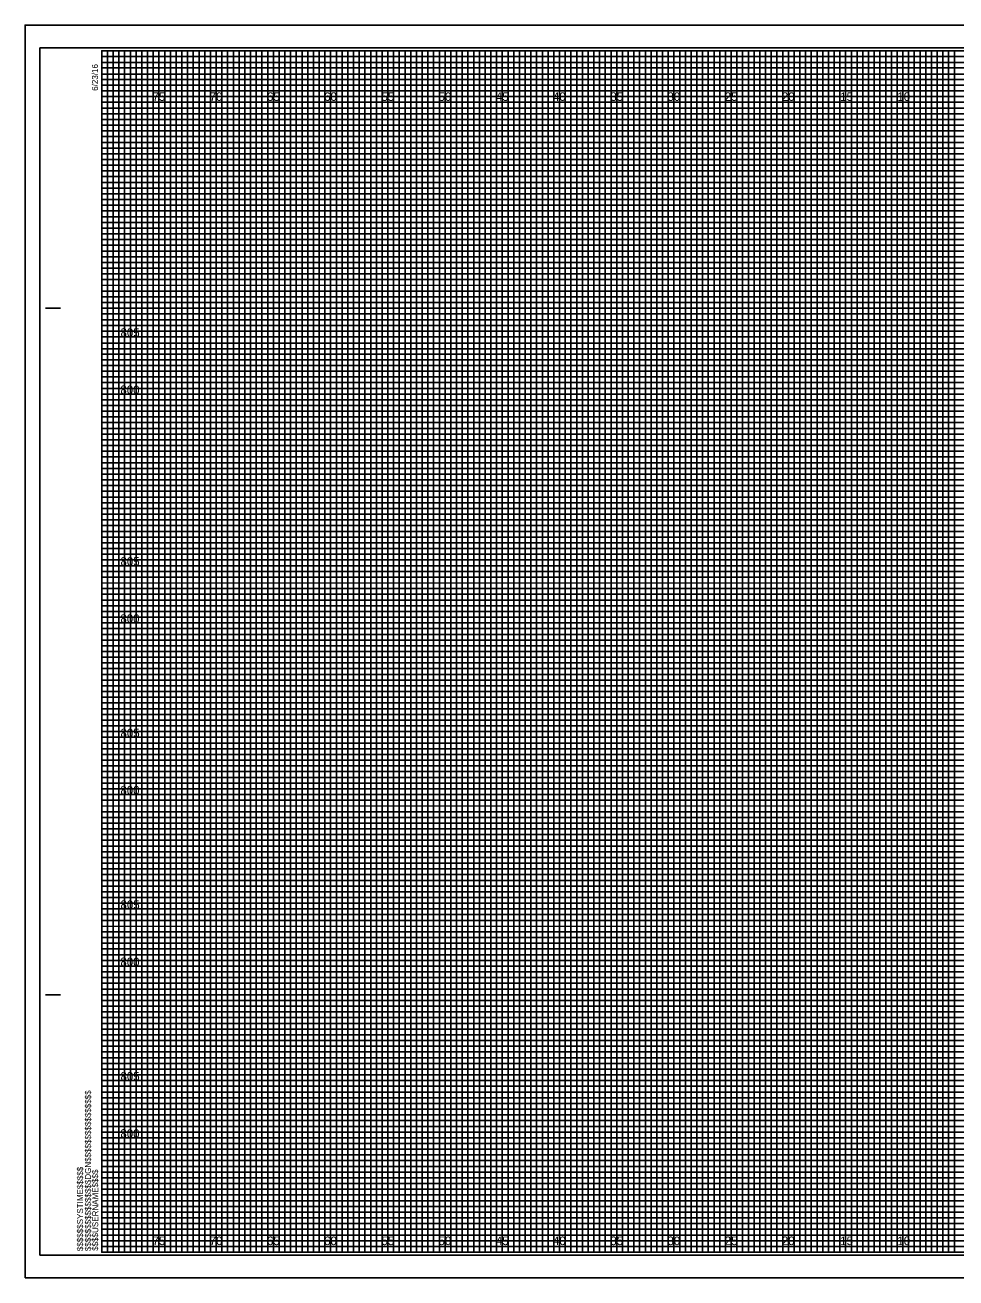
# Model space of a CAD drawing. Extents: x -7 to 162, y -2 to 107.
# Drawn here: x -6.7 to 74.6, y -2.3 to 107.3 of the extents above; entities that cross this region are included whole.
import ezdxf

# ---------------------------------------------------------------- set-up
doc = ezdxf.new("R2010")
doc.units = 0
for name, color, linetype in [('Exist Cross Section Cell', 7, 'Continuous'), ('Exist XS Center Line Elevation Label', 7, 'Continuous'), ('Prop CMT Pvmt Course 1 Wedge', 7, 'Continuous'), ('Prop CMT Pvmt Wedge Surface 1', 7, 'Continuous'), ('Prop XS Hydro Elevations', 7, 'Continuous'), ('Prop XS SE Text', 7, 'Continuous'), ('Prop XS Side Slope Text', 7, 'Continuous'), ('Sheet Cross Section Grid Minor 2 CELL', 7, 'Continuous'), ('Sheet DOT Grid CELL', 7, 'Continuous'), ('Sheet Plot Border Inside CELL', 7, 'Continuous'), ('Sheet Plot Border Outside CELL', 7, 'Continuous')]:
    doc.layers.add(name, color=color, linetype=linetype)

msp = doc.modelspace()

# ---------------------------------------------------------------- linework, layer by layer
at = {"layer": 'Exist Cross Section Cell'}
for p, q in [((5, 105), (0, 105)), ((5, 0), (5, 105)), ((15, 105), (10, 105)), ((10, 105), (10, 0)), ((15, 0), (15, 105)), ((25, 105), (20, 105)), ((20, 105), (20, 0)), ((25, 0), (25, 105)), ((35, 105), (30, 105)), ((30, 105), (30, 0)), ((35, 0), (35, 105)), ((45, 105), (40, 105)), ((40, 105), (40, 0)), ((45, 0), (45, 105)), ((55, 105), (50, 105)), ((50, 105), (50, 0)), ((55, 0), (55, 105)), ((65, 105), (60, 105)), ((60, 105), (60, 0)), ((65, 0), (65, 105)), ((75, 105), (70, 105)), ((70, 105), (70, 0)), ((10, 0), (5, 0)), ((20, 0), (15, 0)), ((30, 0), (25, 0)), ((40, 0), (35, 0)), ((50, 0), (45, 0)), ((60, 0), (55, 0)), ((70, 0), (65, 0))]:
    msp.add_line(p, q, dxfattribs=at)
for points in [[(0, 100), (160, 100), (160, 95), (0, 95)], [(0, 90), (160, 90), (160, 85), (0, 85)], [(0, 80), (160, 80), (160, 75), (0, 75)], [(0, 70), (160, 70), (160, 65), (0, 65)], [(0, 60), (160, 60), (160, 55), (0, 55)], [(0, 50), (160, 50), (160, 45), (0, 45)], [(0, 40), (160, 40), (160, 35), (0, 35)], [(0, 30), (160, 30), (160, 25), (0, 25)], [(0, 20), (160, 20), (160, 15), (0, 15)], [(0, 10), (160, 10), (160, 5), (0, 5)]]:
    msp.add_lwpolyline(points, dxfattribs=at)
at = {"layer": 'Exist XS Center Line Elevation Label'}
for points in [[(0, 105), (2.5, 105), (2.5, 0), (7.5, 0), (7.5, 105), (12.5, 105), (12.5, 0), (17.5, 0), (17.5, 105), (22.5, 105), (22.5, 0), (27.5, 0), (27.5, 105), (32.5, 105), (32.5, 0), (37.5, 0), (37.5, 105), (42.5, 105), (42.5, 0), (47.5, 0), (47.5, 105), (52.5, 105), (52.5, 0), (57.5, 0), (57.5, 105), (62.5, 105), (62.5, 0), (67.5, 0), (67.5, 105), (72.5, 105), (72.5, 0), (77.5, 0)], [(0, 102.5), (137.5, 102.5)], [(0, 92.5), (160, 92.5), (160, 97.5), (0, 97.5)], [(0, 82.5), (160, 82.5), (160, 87.5), (0, 87.5)], [(0, 72.5), (160, 72.5), (160, 77.5), (0, 77.5)], [(0, 62.5), (160, 62.5), (160, 67.5), (0, 67.5)], [(0, 52.5), (160, 52.5), (160, 57.5), (0, 57.5)], [(0, 42.5), (160, 42.5), (160, 47.5), (0, 47.5)], [(0, 32.5), (160, 32.5), (160, 37.5), (0, 37.5)], [(0, 22.5), (160, 22.5), (160, 27.5), (0, 27.5)], [(0, 12.5), (160, 12.5), (160, 17.5), (0, 17.5)], [(0, 2.5), (160, 2.5), (160, 7.5), (0, 7.5)]]:
    msp.add_lwpolyline(points, dxfattribs=at)
at = {"layer": 'Prop CMT Pvmt Wedge Surface 1'}
for p, q in [((161.65, 107.25), (-6.7, 107.25)), ((-6.7, 107.25), (-6.7, -2.25)), ((-6.7, -2.25), (161.65, -2.25))]:
    msp.add_line(p, q, dxfattribs=at)
at = {"layer": 'Prop XS Hydro Elevations'}
for p, q in [((-4.9, 82.5), (-3.65, 82.5)), ((-4.85, 82.5), (-3.6, 82.5)), ((-4.9, 22.5), (-3.65, 22.5)), ((-4.85, 22.5), (-3.6, 22.5)), ((0, 0), (0, 0)), ((0, 0), (0, 0)), ((0, 0), (0, 0)), ((0, 0), (0, 0)), ((0, 0), (0, 0)), ((0, 0), (0, 0)), ((0, 0), (0, 0))]:
    msp.add_line(p, q, dxfattribs=at)
msp.add_lwpolyline([(160, 105), (0, 105), (0, 0), (160, 0)], close=True, dxfattribs=at)
at = {"layer": 'Prop XS Side Slope Text'}
for p, q in [((0, 104.5), (130, 104.5)), ((130, 103.99), (0, 103.99)), ((0, 103.99), (0, 103.5)), ((0, 103.5), (130, 103.5)), ((130, 102.95), (0, 102.95)), ((0, 102.95), (0, 102)), ((0, 102), (160, 102))]:
    msp.add_line(p, q, dxfattribs=at)
for points in [[(0, 101.5), (135, 101.5), (160, 101.5), (160, 101), (0, 101)], [(0, 100.5), (160, 100.5), (160, 99.5), (0, 99.5)], [(0, 99), (160, 99), (160, 98.5), (0, 98.49)], [(0, 98), (160, 98), (160, 97), (0, 97)], [(0, 96.5), (160, 96.5), (160, 96), (0, 96)], [(0, 95.5), (160, 95.5), (160, 94.5), (0, 94.5)], [(0, 94), (160, 94), (160, 93.5), (0, 93.5)], [(0, 93), (160, 93), (160, 92), (0, 92)], [(0, 91.5), (160, 91.5), (160, 91), (0, 91)], [(0, 90.5), (160, 90.5), (160, 89.5), (0, 89.5)], [(0, 89), (160, 89), (160, 88.5), (0, 88.5)], [(0, 88), (160, 88), (160, 86.98), (160, 86.5), (160, 86), (0, 86)], [(0, 87), (160, 87), (160, 86.5), (0, 86.5)], [(0, 85.5), (160, 85.5), (160, 84.5), (0, 84.52)], [(0, 84.52), (160, 84.5), (160, 84), (0, 84)], [(0, 83.5), (160, 83.5), (160, 83), (0, 83)], [(0, 82), (160, 82), (160, 81.5), (0, 81.5)], [(0, 81), (160, 81), (160, 80.5), (0, 80.5)], [(-0.04, 79.45), (160, 79.45), (160, 78.94), (-0.04, 78.94)], [(0, 78.5), (160, 78.5), (160, 78), (0, 78)], [(0, 77), (160, 77), (160, 76.5), (0, 76.5)], [(0, 76), (160, 76), (160, 75.5), (0, 75.5)], [(0, 74.5), (160, 74.5), (160, 74), (0, 74)], [(0, 73.5), (160, 73.5), (160, 73), (0, 73)], [(0, 72), (160, 72), (160, 71.5), (0, 71.5)], [(0, 71), (160, 71), (160, 70.5), (0, 70.5)], [(0, 69.5), (160, 69.5), (160, 68.99), (0, 69)], [(0, 68.5), (160, 68.5), (160, 68), (0, 68)], [(0, 67), (160, 67), (160, 66.5), (0, 66.5)], [(0, 66), (160, 66), (160, 65.5), (0, 65.5)], [(0, 64.5), (160, 64.5), (160, 64), (0, 64)], [(0, 63.5), (160, 63.5), (160, 63), (0, 63)], [(0, 62), (160, 62), (160, 61.5), (0, 61.5)], [(0, 61), (160, 61), (160, 60.5), (0, 60.5)], [(0, 59.5), (160, 59.5), (160, 59), (0, 59)], [(0, 58.5), (160.03, 58.45), (160, 58), (0, 58)], [(0, 57), (160, 57), (160, 56.5), (0, 56.5)], [(0, 56), (160, 56), (160, 55.5), (0, 55.5)], [(0, 54.5), (160, 54.5), (160, 54), (0, 54)], [(0, 53.5), (160, 53.5), (160, 53), (0, 53)], [(0, 52), (160, 52), (160, 51.5), (0, 51.5)], [(0, 51), (160, 51), (160, 50.5), (0, 50.5)], [(0, 49.5), (160, 49.5), (160, 49), (0, 49)], [(0, 48.5), (160, 48.5), (160, 48), (0, 48)], [(0, 47), (160, 47), (160, 46.5), (0, 46.5)], [(0, 46), (160, 46), (160, 45.5), (0, 45.5)], [(0, 44.5), (160, 44.5), (160, 44), (0, 44)], [(0, 43.5), (160, 43.5), (160, 43), (0, 43)], [(0, 42), (160, 42), (160, 41.5), (0, 41.5)], [(0, 41), (160, 41), (160, 40.5), (0, 40.5)], [(0, 39.5), (160, 39.5), (160, 38.99), (0, 39)], [(0, 38.5), (160, 38.5), (160, 38), (0, 38)], [(0, 37), (160, 37), (160, 36.5), (0, 36.5)], [(0, 36), (160, 36), (160, 35.5), (0, 35.5)], [(0, 34.5), (160, 34.5), (160, 34), (0, 34)], [(0, 33.5), (160, 33.5), (160, 33), (0, 33)], [(0, 32), (160, 32), (160, 31.5), (0, 31.5)], [(0, 31), (160, 31), (160, 30.5), (0, 30.5)], [(0, 29.5), (160, 29.5), (160, 29), (0, 29)], [(0, 28.5), (160.03, 28.46), (160, 28), (0, 28)], [(0, 27), (160, 27), (160, 26.5), (0, 26.5)], [(0, 26), (160, 26), (160, 25.5), (0, 25.5)], [(0, 24.5), (160, 24.5), (160, 24), (0, 24)], [(0, 23.5), (160, 23.5), (160, 23), (0, 23)], [(0, 22), (160, 22), (160, 21.5), (0, 21.5)], [(0, 21), (160, 21), (160, 20.5), (0, 20.5)], [(0, 19.5), (160, 19.5), (160, 19), (0, 19)], [(0, 18.5), (160, 18.5), (160, 18), (0, 18)], [(0, 17), (160, 17), (160, 16.5), (0, 16.5)], [(0, 16), (160, 16), (160, 15.5), (0, 15.5)], [(0, 14.5), (160, 14.5), (160, 14), (0, 14)], [(0, 13.5), (160, 13.5), (160, 13), (0, 13)], [(0, 12), (160, 12), (160, 11.5), (0, 11.5)], [(0, 11), (160, 11), (160, 10.5), (0, 10.5)], [(0, 9.5), (160, 9.5), (160, 9), (0, 9)], [(0, 8.5), (160, 8.5), (160, 8), (0, 8)], [(0, 7), (160, 7), (160, 6.5), (0, 6.5)], [(0, 6), (160, 6), (160, 5.5), (0, 5.5)], [(0, 4.5), (160, 4.5), (160, 4), (0, 4)], [(0, 3.5), (160, 3.5), (160, 3), (0, 3)], [(0, 2), (160, 2), (160, 1.5), (0, 1.5)], [(0, 1), (160, 1), (160, 0.5), (0, 0.5)]]:
    msp.add_lwpolyline(points, dxfattribs=at)
at = {"layer": 'Sheet Cross Section Grid Minor 2 CELL'}
for points in [[(0, 0), (0.5, 0), (0.5, 105), (1, 105), (1, 0)], [(1, 0), (1.5, 0), (1.5, 105), (2, 105), (2, 0)], [(2.5, 0), (3, 0), (3, 105), (3.5, 105), (3.5, 0)], [(3.5, 0), (4, 0), (4, 105), (4.5, 105), (4.5, 0)], [(5, 0), (5.5, 0), (5.5, 105), (6, 105), (6, 0)], [(6, 0), (6.5, 0), (6.5, 105), (7, 105), (7, 0)], [(7.5, 0), (8, 0), (8, 105), (8.5, 105), (8.5, 0)], [(8.5, 0), (9, 0), (9, 105), (9.5, 105), (9.5, 0)], [(10, 0), (10.5, 0), (10.5, 105), (11, 105), (11, 0)], [(11, 0), (11.5, 0), (11.5, 105), (12, 105), (12, 0)], [(12.5, 0), (13, 0), (13, 105), (13.5, 105), (13.5, 0)], [(13.5, 0), (14, 0), (14, 105), (14.5, 105), (14.5, 0)], [(15, 0), (15.5, 0), (15.5, 105), (16, 105), (16, 0)], [(16, 0), (16.5, 0), (16.5, 105), (17, 105), (17, 0)], [(17.5, 0), (18, 0), (18, 105), (18.5, 105), (18.5, 0)], [(18.5, 0), (19, 0), (19, 105), (19.5, 105), (19.5, 0)], [(20, 0), (20.5, 0), (20.5, 105), (21, 105), (21, 0)], [(21, 0), (21.5, 0), (21.5, 105), (22, 105), (22, 0)], [(22.5, 0), (23, 0), (23, 105), (23.5, 105), (23.5, 0)], [(23.5, 0), (24, 0), (24, 105), (24.5, 105), (24.5, 0)], [(25, 0), (25.5, 0), (25.5, 105), (26, 105), (26, 0)], [(26, 0), (26.5, 0), (26.5, 105), (27, 105), (27, 0)], [(27.5, 0), (28, 0), (28, 105), (28.5, 105), (28.5, 0)], [(28.5, 0), (29, 0), (29, 105), (29.5, 105), (29.5, 0)], [(30, 0), (30.5, 0), (30.5, 105), (31, 105), (31, 0)], [(31, 0), (31.5, 0), (31.5, 105), (32, 105), (32, 0)], [(32.5, 0), (33, 0), (33, 105), (33.5, 105), (33.5, 0)], [(33.5, 0), (34, 0), (34, 105), (34.5, 105), (34.5, 0)], [(35, 0), (35.5, 0), (35.5, 105), (36, 105), (36, 0)], [(36, 0), (36.5, 0), (36.5, 105), (37, 105), (37, 0)], [(37.5, 0), (38, 0), (38, 105), (38.5, 105), (38.5, 0)], [(38.5, 0), (39, 0), (39, 105), (39.5, 105), (39.5, 0)], [(40, 0), (40.5, 0), (40.5, 105), (41, 105), (41, 0)], [(41, 0), (41.5, 0), (41.5, 105), (42, 105), (42, 0)], [(42.5, 0), (43, 0), (43, 105), (43.5, 105), (43.5, 0)], [(43.5, 0), (44, 0), (44, 105), (44.5, 105), (44.5, 0)], [(45, 0), (45.5, 0), (45.5, 105), (46, 105), (46, 0)], [(46, 0), (46.5, 0), (46.5, 105), (47, 105), (47, 0)], [(47.5, 0), (48, 0), (48, 105), (48.5, 105), (48.5, 0)], [(48.5, 0), (49, 0), (49, 105), (49.5, 105), (49.5, 0)], [(50, 0), (50.5, 0), (50.5, 105), (51, 105), (51, 0)], [(51, 0), (51.5, 0), (51.5, 105), (52, 105), (52, 0)], [(52.5, 0), (53, 0), (53, 105), (53.5, 105), (53.5, 0)], [(53.5, 0), (54, 0), (54, 105), (54.5, 105), (54.5, 0)], [(55, 0), (55.5, 0), (55.5, 105), (56, 105), (56, 0)], [(56, 0), (56.5, 0), (56.5, 105), (57, 105), (57, 0)], [(57.5, 0), (58, 0), (58, 105), (58.5, 105), (58.5, 0)], [(58.5, 0), (59, 0), (59, 105), (59.5, 105), (59.5, 0)], [(60, 0), (60.5, 0), (60.5, 105), (61, 105), (61, 0)], [(61, 0), (61.5, 0), (61.5, 105), (62, 105), (62, 0)], [(62.5, 0), (63, 0), (63, 105), (63.5, 105), (63.5, 0)], [(63.5, 0), (64, 0), (64, 105), (64.5, 105), (64.5, 0)], [(65, 0), (65.5, 0), (65.5, 105), (66, 105), (66, 0)], [(66, 0), (66.5, 0), (66.5, 105), (67, 105), (67, 0)], [(67.5, 0), (68, 0), (68, 105), (68.5, 105), (68.5, 0)], [(68.5, 0), (69, 0), (69, 105), (69.5, 105), (69.5, 0)], [(70, 0), (70.5, 0), (70.5, 105), (71, 105), (71, 0)], [(71, 0), (71.5, 0), (71.5, 105), (72, 105), (72, 0)], [(72.5, 0), (73, 0), (73, 105), (73.5, 105), (73.5, 0)], [(73.5, 0), (74, 0), (74, 105), (74.5, 105), (74.5, 0)]]:
    msp.add_lwpolyline(points, dxfattribs=at)
at = {"layer": 'Sheet DOT Grid CELL'}
for p, q in [((5, 0), (5, 105)), ((10, 0), (10, 105)), ((15, 0), (15, 105)), ((20, 0), (20, 105)), ((25, 0), (25, 105)), ((30, 0), (30, 105)), ((35, 0), (35, 105)), ((40, 0), (40, 105)), ((45, 0), (45, 105)), ((50, 0), (50, 105)), ((55, 0), (55, 105)), ((60, 0), (60, 105)), ((65, 0), (65, 105)), ((70, 0), (70, 105)), ((0, 100), (160, 100)), ((0, 95), (160, 95)), ((0, 90), (160, 90)), ((0, 85), (160, 85)), ((0, 80), (160, 80)), ((0, 75), (160, 75)), ((0, 70), (160, 70)), ((0, 65), (160, 65)), ((0, 60), (160, 60)), ((0, 55), (160, 55)), ((0, 50), (160, 50)), ((0, 45), (160, 45)), ((0, 40), (160, 40)), ((0, 35), (160, 35)), ((0, 30), (160, 30)), ((0, 25), (160, 25)), ((0, 20), (160, 20)), ((0, 15), (160, 15)), ((0, 10), (160, 10)), ((0, 5), (160, 5))]:
    msp.add_line(p, q, dxfattribs=at)
at = {"layer": 'Sheet Plot Border Inside CELL'}
msp.add_lwpolyline([(-5.4, -0.25), (161.2, -0.25), (161.2, 105.25), (-5.4, 105.25)], close=True, dxfattribs=at)
at = {"layer": 'Sheet Plot Border Outside CELL'}
msp.add_lwpolyline([(-6.7, -2.25), (161.65, -2.25), (161.65, 107.25), (-6.7, 107.25)], close=True, dxfattribs=at)

# ---------------------------------------------------------------- texts
at = {"layer": 'Prop CMT Pvmt Course 1 Wedge'}
for s, p in [('805', (1.64, 80)), ('800', (1.63, 75)), ('805', (1.64, 60)), ('800', (1.63, 55)), ('805', (1.64, 45)), ('800', (1.63, 40)), ('805', (1.64, 30)), ('800', (1.63, 25)), ('805', (1.64, 15)), ('800', (1.63, 10))]:
    msp.add_text(s, height=0.75, dxfattribs=at).set_placement(p)
at = {"layer": 'Prop XS Hydro Elevations'}
for s, p in [('6/23/16', (-0.33, 101.5)), ('$$$$$$$$$$$$$$$$DGN$$$$$$$$$$$$$$$$', (-0.94, 0.09)), ('$$$$$$SYSTIME$$$$$', (-1.63, 0.09)), ('$$$$USERNAME$$$$', (-0.31, 0.12))]:
    msp.add_text(s, height=0.525, rotation=90, dxfattribs=at).set_placement(p)
at = {"layer": 'Prop XS SE Text'}
for s, p in [('75', (4.44, 100.62)), ('70', (9.43, 100.62)), ('65', (14.44, 100.62)), ('60', (19.43, 100.62)), ('55', (24.44, 100.62)), ('50', (29.43, 100.62)), ('45', (34.44, 100.62)), ('40', (39.43, 100.62)), ('35', (44.44, 100.62)), ('30', (49.43, 100.62)), ('25', (54.44, 100.62)), ('20', (59.43, 100.62)), ('15', (64.53, 100.62)), ('10', (69.52, 100.62)), ('75', (4.44, 0.62)), ('70', (9.43, 0.62)), ('65', (14.44, 0.62)), ('60', (19.43, 0.62)), ('55', (24.44, 0.62)), ('50', (29.43, 0.62)), ('45', (34.44, 0.62)), ('40', (39.43, 0.62)), ('35', (44.44, 0.62)), ('30', (49.43, 0.62)), ('25', (54.44, 0.62)), ('20', (59.43, 0.62)), ('15', (64.53, 0.62)), ('10', (69.52, 0.62))]:
    msp.add_text(s, height=0.75, dxfattribs=at).set_placement(p)

doc.saveas('drawing.dxf')
